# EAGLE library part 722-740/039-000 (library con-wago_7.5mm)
Serie 722, Federleiste mit Verriegelungsklinken / Series 722, Female connector with locking levers Polzahl / Pole No.: 10 Bemessungsspannung / Rated Voltage: 400 V Nennstrom / Nominal Current: 12 A Farbe / Color: xxxx / xxxx Stand: 01.01.2012. Die jeweils aktuellen Daten zu diesem Artikel finden Sie in unserem Produktkatalog, den Sie unter www.wago.com einsehen können. As of: 01/01/2012. Please find the newest data for this article in our product catalogue, which can be viewed under www.wago.com.
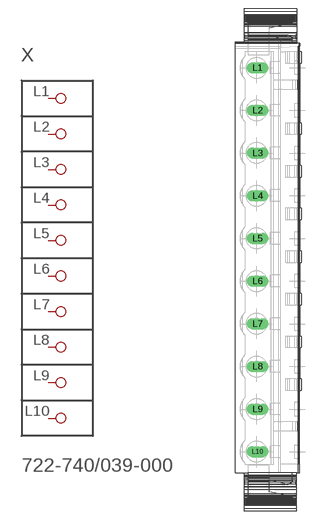
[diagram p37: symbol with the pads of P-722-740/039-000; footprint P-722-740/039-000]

Designator prefix X

## 722-740/039-000  [P-722-740/039-000]
L1  P1
L2  P2
L3  P3
L4  P4
L5  P5
L6  P6
L7  P7
L8  P8
L9  P9
L10  P10

## Footprint P-722-740/039-000 (pad centres in mm)
drill 1.3 long: L1 -2.196,33.75; L2 -2.196,26.25; L3 -2.196,18.75; L4 -2.196,11.25; L5 -2.196,3.75; L6 -2.196,-3.75; L7 -2.196,-11.25; L8 -2.196,-18.75; L9 -2.196,-26.25; L10 -2.196,-33.75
